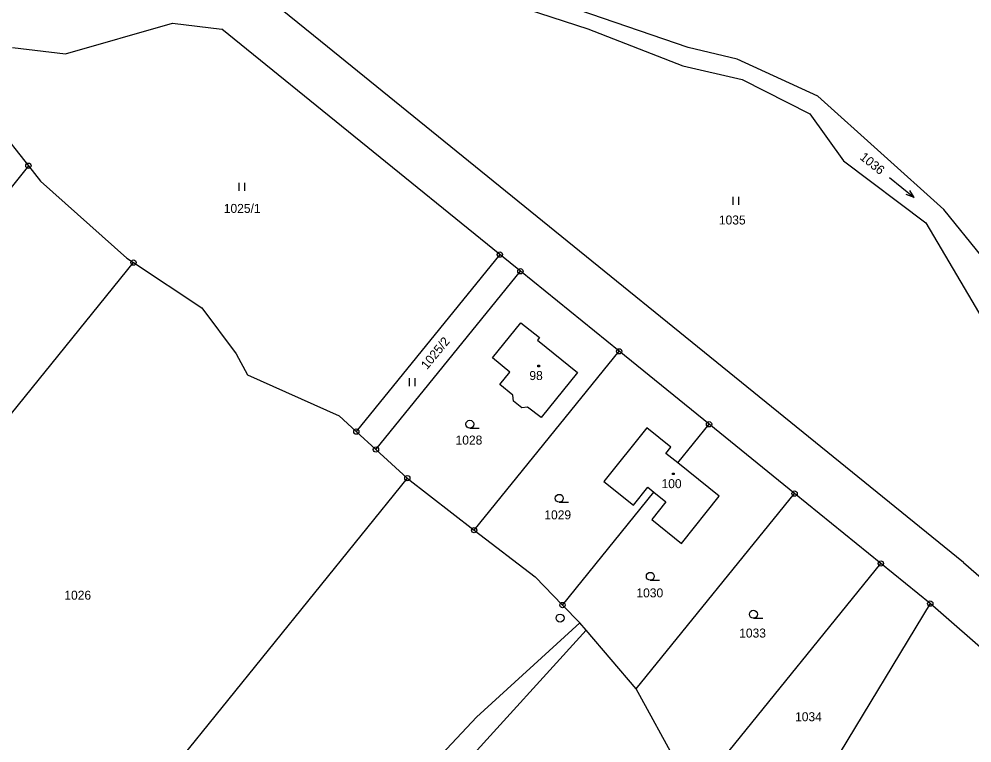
# Model space of a CAD drawing. Extents: x -796130 to -793145, y -1109506 to -1106267.
# Drawn here: x -794845 to -794664.8, y -1107475.5 to -1107338.6 of the extents above; entities that cross this region are included whole.
import ezdxf

# ---------------------------------------------------------------- set-up
doc = ezdxf.new("R2010")
doc.units = 0
for name, color, linetype in [('Vrstva 1', 7, 'Continuous'), ('Vrstva 14', 7, 'Continuous'), ('Vrstva 15', 7, 'Continuous'), ('Vrstva 23', 7, 'Continuous'), ('Vrstva 25', 7, 'Continuous'), ('Vrstva 28', 7, 'Continuous')]:
    doc.layers.add(name, color=color, linetype=linetype)

msp = doc.modelspace()

# ---------------------------------------------------------------- linework, layer by layer
at = {"layer": 'Vrstva 1'}
for p, q in [((-794787.99, -1107342.8), (-794811.97, -1107323.36)), ((-794718.47, -1107344.01), (-794758.4, -1107330.29)), ((-794762.67, -1107332.27), (-794737.42, -1107340.51)), ((-794836.19, -1107345.24), (-794815.98, -1107339.42)), ((-794815.98, -1107339.42), (-794806.61, -1107340.57)), ((-794754.08, -1107383.17), (-794806.61, -1107340.57)), ((-794737.42, -1107340.51), (-794719.5, -1107347.49)), ((-794666.42, -1107441.4), (-794787.99, -1107342.8)), ((-794846.19, -1107344.03), (-794836.19, -1107345.24)), ((-794709.24, -1107346.25), (-794718.47, -1107344.01)), ((-794693.95, -1107353.22), (-794709.24, -1107346.25)), ((-794719.5, -1107347.49), (-794708.3, -1107350.08)), ((-794855.76, -1107350.49), (-794843.19, -1107366.37)), ((-794708.3, -1107350.08), (-794695.47, -1107356.55)), ((-794670.17, -1107374.63), (-794693.95, -1107353.22)), ((-794695.47, -1107356.55), (-794689.1, -1107365.45)), ((-794843.19, -1107366.37), (-794931.23, -1107475.15)), ((-794843.19, -1107366.37), (-794840.88, -1107369.29)), ((-794689.1, -1107365.45), (-794673.54, -1107377.14)), ((-794840.88, -1107369.29), (-794824.59, -1107383.84)), ((-794662.94, -1107383.6), (-794670.17, -1107374.63)), ((-794673.54, -1107377.14), (-794666.34, -1107389.48)), ((-794903.71, -1107484.02), (-794823.32, -1107384.68)), ((-794824.59, -1107383.84), (-794823.32, -1107384.68)), ((-794823.32, -1107384.68), (-794810.41, -1107393.23)), ((-794754.08, -1107383.17), (-794781.21, -1107416.64)), ((-794750.2, -1107386.32), (-794754.08, -1107383.17)), ((-794777.51, -1107420.02), (-794750.2, -1107386.32)), ((-794731.53, -1107401.46), (-794750.2, -1107386.32)), ((-794666.34, -1107389.48), (-794659.26, -1107401.45)), ((-794810.41, -1107393.23), (-794803.95, -1107401.92)), ((-794755.5, -1107402.72), (-794750.09, -1107396.06)), ((-794750.09, -1107396.06), (-794746.58, -1107398.87)), ((-794746.58, -1107398.87), (-794746.95, -1107399.35)), ((-794746.95, -1107399.35), (-794739.39, -1107405.46)), ((-794803.95, -1107401.92), (-794801.77, -1107405.93)), ((-794758.94, -1107435.27), (-794731.53, -1107401.46)), ((-794752.2, -1107405.4), (-794755.5, -1107402.72)), ((-794714.53, -1107415.25), (-794731.53, -1107401.46)), ((-794801.77, -1107405.93), (-794784.46, -1107413.66)), ((-794754.07, -1107407.74), (-794752.2, -1107405.4)), ((-794739.39, -1107405.46), (-794746.3, -1107414)), ((-794751.6, -1107409.75), (-794754.07, -1107407.74)), ((-794751.52, -1107410.91), (-794751.6, -1107409.75)), ((-794749.94, -1107412.17), (-794751.52, -1107410.91)), ((-794781.21, -1107416.64), (-794784.46, -1107413.66)), ((-794748.83, -1107412.01), (-794749.94, -1107412.17)), ((-794746.3, -1107414), (-794748.83, -1107412.01)), ((-794720.46, -1107422.56), (-794714.53, -1107415.25)), ((-794698.36, -1107428.36), (-794714.53, -1107415.25)), ((-794777.51, -1107420.02), (-794781.21, -1107416.64)), ((-794726.31, -1107415.92), (-794734.41, -1107426.05)), ((-794721.74, -1107419.58), (-794726.31, -1107415.92)), ((-794777.51, -1107420.02), (-794771.57, -1107425.45)), ((-794722.7, -1107420.77), (-794721.74, -1107419.58)), ((-794720.46, -1107422.56), (-794722.7, -1107420.77)), ((-794712.61, -1107428.84), (-794720.46, -1107422.56)), ((-794771.57, -1107425.45), (-794838.71, -1107508.42)), ((-794771.57, -1107425.45), (-794758.94, -1107435.27)), ((-794734.41, -1107426.05), (-794728.8, -1107430.53)), ((-794728.8, -1107430.53), (-794726.12, -1107427.17)), ((-794726.12, -1107427.17), (-794724.95, -1107428.1)), ((-794742.24, -1107449.43), (-794724.95, -1107428.1)), ((-794728.31, -1107465.29), (-794698.36, -1107428.36)), ((-794724.95, -1107428.1), (-794722.68, -1107429.92)), ((-794719.76, -1107437.77), (-794712.61, -1107428.84)), ((-794682.07, -1107441.58), (-794698.36, -1107428.36)), ((-794722.68, -1107429.92), (-794725.36, -1107433.28)), ((-794725.36, -1107433.28), (-794719.76, -1107437.77)), ((-794758.94, -1107435.27), (-794747.41, -1107444.13)), ((-794717.39, -1107485.15), (-794682.07, -1107441.58)), ((-794672.72, -1107449.16), (-794682.07, -1107441.58)), ((-794666.42, -1107441.4), (-794638.46, -1107465.89)), ((-794747.41, -1107444.13), (-794742.24, -1107449.43)), ((-794742.24, -1107449.43), (-794738.96, -1107452.79)), ((-794672.72, -1107449.16), (-794706.54, -1107504.86)), ((-794653.59, -1107465.98), (-794672.72, -1107449.16)), ((-794758.5, -1107470.63), (-794738.96, -1107452.79)), ((-794737.76, -1107454.19), (-794738.96, -1107452.79)), ((-794803.77, -1107526.73), (-794737.76, -1107454.19)), ((-794728.31, -1107465.29), (-794737.76, -1107454.19)), ((-794717.39, -1107485.15), (-794728.31, -1107465.29)), ((-794768.82, -1107481.58), (-794758.5, -1107470.63))]:
    msp.add_line(p, q, dxfattribs=at)
at = {"layer": 'Vrstva 23'}
for p, q in [((-794680.406, -1107368.574), (-794675.773, -1107372.385)), ((-794803.34, -1107371.12), (-794803.34, -1107369.62)), ((-794802.34, -1107369.62), (-794802.34, -1107371.12)), ((-794675.773, -1107372.385), (-794677.249, -1107371.819)), ((-794675.773, -1107372.385), (-794676.613, -1107371.046)), ((-794710, -1107373.75), (-794710, -1107372.25)), ((-794709, -1107372.25), (-794709, -1107373.75)), ((-794771.15, -1107408.05), (-794771.15, -1107406.55)), ((-794770.15, -1107406.55), (-794770.15, -1107408.05)), ((-794759.75, -1107415.99), (-794758, -1107415.99)), ((-794742.85, -1107430), (-794741.1, -1107430)), ((-794725.64, -1107444.75), (-794723.89, -1107444.75)), ((-794706.15, -1107451.92), (-794704.4, -1107451.92))]:
    msp.add_line(p, q, dxfattribs=at)
for centre in [(-794759.75, -1107415.24), (-794742.85, -1107429.25), (-794725.64, -1107444), (-794706.15, -1107451.17)]:
    msp.add_circle(centre, 0.75, dxfattribs=at)
at = {"layer": 'Vrstva 25'}
for p, q in [((-794746.87, -1107404.07), (-794746.57, -1107404.07)), ((-794746.87, -1107404.37), (-794746.87, -1107404.07)), ((-794746.57, -1107404.37), (-794746.87, -1107404.37)), ((-794746.57, -1107404.07), (-794746.57, -1107404.37)), ((-794721.45, -1107424.47), (-794721.15, -1107424.47)), ((-794721.45, -1107424.77), (-794721.45, -1107424.47)), ((-794721.15, -1107424.77), (-794721.45, -1107424.77)), ((-794721.15, -1107424.47), (-794721.15, -1107424.77))]:
    msp.add_line(p, q, dxfattribs=at)
at = {"layer": 'Vrstva 28'}
for centre, radius in [((-794843.19, -1107366.37), 0.5), ((-794843.19, -1107366.37), 0.01), ((-794754.08, -1107383.17), 0.5), ((-794823.32, -1107384.68), 0.5), ((-794823.32, -1107384.68), 0.01), ((-794754.08, -1107383.17), 0.01), ((-794750.2, -1107386.32), 0.5), ((-794750.2, -1107386.32), 0.01), ((-794731.53, -1107401.46), 0.5), ((-794731.53, -1107401.46), 0.01), ((-794714.53, -1107415.25), 0.5), ((-794714.53, -1107415.25), 0.01), ((-794781.21, -1107416.64), 0.5), ((-794781.21, -1107416.64), 0.01), ((-794777.51, -1107420.02), 0.5), ((-794777.51, -1107420.02), 0.01), ((-794771.57, -1107425.45), 0.5), ((-794771.57, -1107425.45), 0.01), ((-794698.36, -1107428.36), 0.5), ((-794698.36, -1107428.36), 0.01), ((-794758.94, -1107435.27), 0.5), ((-794758.94, -1107435.27), 0.01), ((-794682.07, -1107441.58), 0.5), ((-794682.07, -1107441.58), 0.01), ((-794742.24, -1107449.43), 0.5), ((-794742.24, -1107449.43), 0.01), ((-794672.72, -1107449.16), 0.5), ((-794672.72, -1107449.16), 0.5), ((-794672.72, -1107449.16), 0.01), ((-794672.72, -1107449.16), 0.01), ((-794742.7, -1107451.9), 0.75), ((-794742.7, -1107451.9), 0.01)]:
    msp.add_circle(centre, radius, dxfattribs=at)

# ---------------------------------------------------------------- texts
at = {"layer": 'Vrstva 14'}
for s, rotation, p in [('1036', 321.3, (-794686.169, -1107365.01)), ('1025/2', 50.66235, (-794767.831, -1107405.01))]:
    msp.add_text(s, height=1.7, rotation=rotation, dxfattribs=at).set_placement(p)
for s, p in [('1025/1', (-794806.262, -1107375.29)), ('1035', (-794712.675, -1107377.48)), ('1028', (-794762.449, -1107419.09)), ('1029', (-794745.669, -1107433.23)), ('1026', (-794836.399, -1107448.42)), ('1030', (-794728.268, -1107447.98)), ('1033', (-794708.839, -1107455.58)), ('1034', (-794698.275, -1107471.4))]:
    msp.add_text(s, height=1.7, dxfattribs=at).set_placement(p)
at = {"layer": 'Vrstva 15'}
for s, p in [('98', (-794748.497, -1107406.89)), ('100', (-794723.518, -1107427.33))]:
    msp.add_text(s, height=1.7, dxfattribs=at).set_placement(p)

doc.saveas('drawing.dxf')
